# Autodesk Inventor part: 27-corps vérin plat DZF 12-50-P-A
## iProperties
Created: 2011-02
Part Number: 27-corps vérin plat DZF 12-50-P-A
Document SubType Name: Modeling
Designer: eric
Density: 1 g/cm^3
Author: eric
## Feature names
1. Base1
